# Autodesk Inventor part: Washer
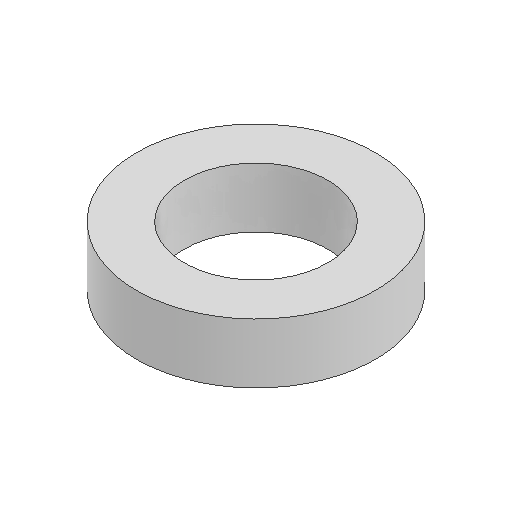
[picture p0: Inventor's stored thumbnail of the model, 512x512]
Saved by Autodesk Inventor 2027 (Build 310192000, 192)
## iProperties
Created: 2026-05
Part Number: Washer
Material: Generic
Document SubType Name: Modeling
Designer: kavit
Density: 1 g/cm^3
Appearance: Default
Author: kavit
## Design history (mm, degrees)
sketch "Sketch1"
  geometry: C1 r 10 at (0, 0); C2 r 6 at (0, 0); 1 further point
  constraints: 2 centre point, 2 coincident
  dimensions: "d0" = 20 diameter of C1; "d1" = 12 diameter of C2
extrude "Extrusion1" new body sketch "Sketch1" distance "d2" = 5; taper "d3" = 0 deg
body "Solid1"
